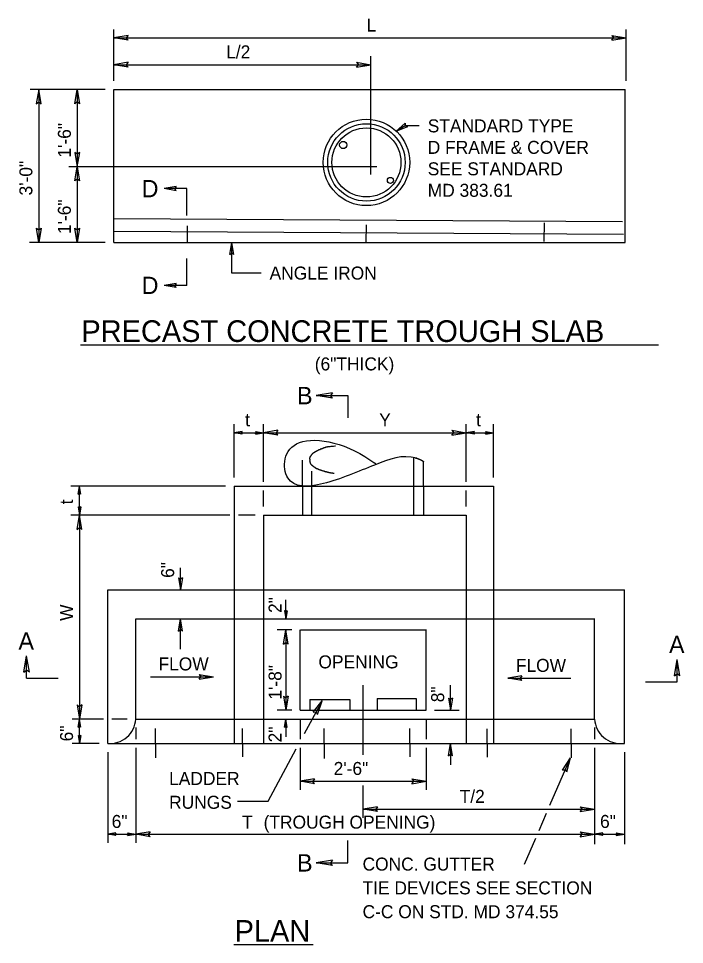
# Model space of a CAD drawing. Extents: x 5.8 to 18, y -5.2 to 5.4.
# Drawn here: x 5.94 to 9.015, y 0.977 to 5.255 of the extents above; entities that cross this region are included whole.
import ezdxf

# ---------------------------------------------------------------- set-up
doc = ezdxf.new("R2010")
doc.units = 0
for name, color, linetype in [('DETL-DIMS', 7, 'Continuous'), ('DETL-LINE', 7, 'Continuous'), ('DETL-NOTE', 7, 'Continuous'), ('DETL-TITL', 7, 'Continuous')]:
    doc.layers.add(name, color=color, linetype=linetype)

msp = doc.modelspace()

# ---------------------------------------------------------------- linework, layer by layer
at = {"layer": 'DETL-DIMS'}
for p, q in [((6.3798, 4.9667), (6.3798, 5.205)), ((6.4456, 5.1768), (6.3798, 5.1658)), ((6.4456, 5.1768), (6.4374, 5.1658)), ((8.6793, 5.1768), (8.7452, 5.1658)), ((8.6793, 5.1768), (8.6876, 5.1658)), ((8.7452, 4.9667), (8.7452, 5.205)), ((6.3798, 5.1658), (8.7452, 5.1658)), ((6.4456, 5.1548), (6.3798, 5.1658)), ((6.4456, 5.1548), (6.4374, 5.1658)), ((8.6793, 5.1548), (8.7452, 5.1658)), ((8.6793, 5.1548), (8.6876, 5.1658)), ((6.4456, 5.0529), (6.3798, 5.0419)), ((6.4456, 5.0529), (6.4374, 5.0419)), ((7.501, 5.0529), (7.5669, 5.0419)), ((7.501, 5.0529), (7.5092, 5.0419)), ((7.5669, 4.5349), (7.5669, 5.0811)), ((6.3798, 5.0419), (7.5669, 5.0419)), ((6.4456, 5.0309), (6.3798, 5.0419)), ((6.4456, 5.0309), (6.4374, 5.0419)), ((7.501, 5.0309), (7.5669, 5.0419)), ((7.501, 5.0309), (7.5092, 5.0419)), ((6.3405, 4.9274), (5.9938, 4.9274)), ((6.0331, 4.9274), (6.0217, 4.8616)), ((6.0331, 4.9274), (6.0329, 4.2209)), ((6.0436, 4.8615), (6.0331, 4.9274)), ((6.1995, 4.8616), (6.2108, 4.9274)), ((6.2108, 4.9274), (6.2107, 4.5707)), ((6.2108, 4.9274), (6.2214, 4.8615)), ((6.0217, 4.8616), (6.0327, 4.8698)), ((6.0327, 4.8698), (6.0436, 4.8615)), ((6.2105, 4.8698), (6.1995, 4.8616)), ((6.2214, 4.8615), (6.2105, 4.8698)), ((7.6825, 4.7332), (7.7256, 4.771)), ((7.7245, 4.7592), (7.6825, 4.7332)), ((7.7355, 4.755), (7.6825, 4.7332)), ((7.7256, 4.771), (7.7245, 4.7592)), ((7.7245, 4.7592), (7.7355, 4.755)), ((7.7903, 4.7592), (7.7245, 4.7592)), ((6.2111, 4.6283), (6.2002, 4.6367)), ((6.2002, 4.6367), (6.2107, 4.5707)), ((6.2107, 4.5707), (6.2221, 4.6365)), ((6.2221, 4.6365), (6.2111, 4.6283)), ((7.5947, 4.5707), (6.1715, 4.5707)), ((6.1994, 4.5049), (6.2107, 4.5707)), ((6.2107, 4.5707), (6.2213, 4.5047)), ((6.2107, 4.5707), (6.2107, 4.2209)), ((6.2104, 4.513), (6.1994, 4.5049)), ((6.2213, 4.5047), (6.2104, 4.513)), ((6.6684, 4.4787), (6.612, 4.4692)), ((6.7164, 4.4692), (6.612, 4.4692)), ((6.6684, 4.4598), (6.612, 4.4692)), ((6.6684, 4.4787), (6.6614, 4.4692)), ((6.6684, 4.4598), (6.6614, 4.4692)), ((6.7164, 4.3452), (6.7164, 4.4692)), ((6.0329, 4.2209), (6.0223, 4.2868)), ((6.0223, 4.2868), (6.0333, 4.2785)), ((6.0443, 4.2867), (6.0329, 4.2209)), ((6.0333, 4.2785), (6.0443, 4.2867)), ((6.2107, 4.2209), (6.2001, 4.2868)), ((6.2001, 4.2868), (6.211, 4.2785)), ((6.222, 4.2867), (6.2107, 4.2209)), ((6.211, 4.2785), (6.222, 4.2867)), ((6.3405, 4.2209), (5.9897, 4.2209)), ((6.9151, 4.1644), (6.9245, 4.2209)), ((6.9245, 4.0792), (6.9245, 4.2209)), ((6.9339, 4.1644), (6.9245, 4.2209)), ((6.9151, 4.1644), (6.9245, 4.1714)), ((6.9339, 4.1644), (6.9245, 4.1714)), ((6.7164, 4.0223), (6.7164, 4.1463)), ((7.0599, 4.0792), (6.9245, 4.0792)), ((6.6684, 4.0317), (6.612, 4.0223)), ((6.7164, 4.0223), (6.612, 4.0223)), ((6.6684, 4.0129), (6.612, 4.0223)), ((6.6684, 4.0317), (6.6614, 4.0223)), ((6.6684, 4.0129), (6.6614, 4.0223)), ((7.3896, 3.5257), (7.3144, 3.5131)), ((7.3144, 3.5131), (7.46, 3.5131)), ((7.3896, 3.5006), (7.3144, 3.5131)), ((7.3896, 3.5257), (7.3802, 3.5131)), ((7.3896, 3.5006), (7.3802, 3.5131)), ((7.46, 3.5131), (7.46, 3.4104)), ((6.9352, 3.1341), (6.9352, 3.381)), ((7.0717, 3.1145), (7.0717, 3.381)), ((8.007, 3.1145), (8.007, 3.381)), ((8.1335, 3.1341), (8.1335, 3.381)), ((6.9729, 3.348), (6.9352, 3.3418)), ((6.9352, 3.3418), (7.0717, 3.3418)), ((6.9729, 3.3355), (6.9352, 3.3418)), ((6.9729, 3.348), (6.9682, 3.3418)), ((6.9729, 3.3355), (6.9682, 3.3418)), ((7.034, 3.348), (7.0717, 3.3418)), ((7.034, 3.348), (7.0387, 3.3418)), ((7.034, 3.3355), (7.0717, 3.3418)), ((7.034, 3.3355), (7.0387, 3.3418)), ((7.1376, 3.3527), (7.0717, 3.3418)), ((7.0717, 3.3418), (8.007, 3.3418)), ((7.1376, 3.3308), (7.0717, 3.3418)), ((7.1376, 3.3527), (7.1293, 3.3418)), ((7.1376, 3.3308), (7.1293, 3.3418)), ((7.9411, 3.3527), (8.007, 3.3418)), ((7.9411, 3.3527), (7.9494, 3.3418)), ((7.9411, 3.3308), (8.007, 3.3418)), ((7.9411, 3.3308), (7.9494, 3.3418)), ((8.0447, 3.348), (8.007, 3.3418)), ((8.007, 3.3418), (8.1335, 3.3418)), ((8.0447, 3.3355), (8.007, 3.3418)), ((8.0447, 3.348), (8.04, 3.3418)), ((8.0447, 3.3355), (8.04, 3.3418)), ((8.0958, 3.348), (8.1335, 3.3418)), ((8.0958, 3.348), (8.1005, 3.3418)), ((8.0958, 3.3355), (8.1335, 3.3418)), ((8.0958, 3.3355), (8.1005, 3.3418)), ((6.896, 3.0949), (6.1815, 3.0949)), ((6.2145, 3.0573), (6.2207, 3.0949)), ((6.2207, 2.961), (6.2207, 3.0949)), ((6.227, 3.0573), (6.2207, 3.0949)), ((6.2145, 3.0573), (6.2207, 3.062)), ((6.227, 3.0573), (6.2207, 3.062)), ((7.0717, 3.0002), (7.0717, 3.0753)), ((8.007, 3.0002), (8.007, 3.0753)), ((6.2145, 2.9987), (6.2207, 2.961)), ((6.2145, 2.9987), (6.2207, 2.994)), ((6.227, 2.9987), (6.2207, 2.961)), ((6.227, 2.9987), (6.2207, 2.994)), ((6.9156, 2.961), (6.1815, 2.961)), ((6.2098, 2.8951), (6.2207, 2.961)), ((6.2317, 2.8951), (6.2207, 2.961)), ((6.2207, 2.961), (6.2207, 2.0182)), ((7.0325, 2.961), (6.9548, 2.961)), ((6.2098, 2.8951), (6.2207, 2.9034)), ((6.2317, 2.8951), (6.2207, 2.9034)), ((6.6876, 2.6154), (6.6876, 2.7173)), ((6.6782, 2.6718), (6.6876, 2.6154)), ((6.6782, 2.6718), (6.6876, 2.6648)), ((6.697, 2.6718), (6.6876, 2.6154)), ((6.697, 2.6718), (6.6876, 2.6648)), ((7.1741, 2.4819), (7.1741, 2.5697)), ((6.6782, 2.4254), (6.6876, 2.4819)), ((6.6876, 2.3418), (6.6876, 2.4819)), ((6.697, 2.4254), (6.6876, 2.4819)), ((7.168, 2.5196), (7.1741, 2.4819)), ((7.168, 2.5196), (7.1743, 2.5149)), ((7.1806, 2.5195), (7.1741, 2.4819)), ((7.1806, 2.5195), (7.1743, 2.5149)), ((6.6782, 2.4254), (6.6876, 2.4325)), ((6.697, 2.4254), (6.6876, 2.4325)), ((7.2013, 2.4306), (7.1349, 2.4306)), ((7.1627, 2.3648), (7.1741, 2.4306)), ((7.1846, 2.3646), (7.1741, 2.4306)), ((7.1741, 2.4306), (7.1741, 2.0592)), ((7.1627, 2.3648), (7.1737, 2.3729)), ((7.1846, 2.3646), (7.1737, 2.3729)), ((5.9645, 2.2351), (5.977, 2.3104)), ((5.977, 2.2074), (5.977, 2.3104)), ((5.9896, 2.2351), (5.977, 2.3104)), ((8.9691, 2.2186), (8.9816, 2.2939)), ((8.9816, 2.1909), (8.9816, 2.2939)), ((8.9942, 2.2186), (8.9816, 2.2939)), ((5.9645, 2.2351), (5.977, 2.2445)), ((5.9896, 2.2351), (5.977, 2.2445)), ((6.7736, 2.225), (6.8395, 2.214)), ((6.7736, 2.225), (6.7819, 2.214)), ((8.9691, 2.2186), (8.9816, 2.228)), ((8.9942, 2.2186), (8.9816, 2.228)), ((5.977, 2.2074), (6.1227, 2.2074)), ((6.5485, 2.214), (6.8395, 2.214)), ((6.7736, 2.203), (6.8395, 2.214)), ((6.7736, 2.203), (6.7819, 2.214)), ((8.2646, 2.2184), (8.1987, 2.2074)), ((8.1987, 2.2074), (8.4899, 2.2074)), ((8.2646, 2.1964), (8.1987, 2.2074)), ((8.2646, 2.2184), (8.2564, 2.2074)), ((8.2646, 2.1964), (8.2564, 2.2074)), ((8.8359, 2.1909), (8.9816, 2.1909)), ((7.5314, 1.8537), (7.5314, 2.1756)), ((7.9347, 2.0592), (7.9347, 2.1754)), ((7.1635, 2.1252), (7.1741, 2.0592)), ((7.1635, 2.1252), (7.1745, 2.1169)), ((7.1855, 2.125), (7.1741, 2.0592)), ((7.1855, 2.125), (7.1745, 2.1169)), ((7.3413, 2.1029), (7.2591, 1.9502)), ((7.3004, 2.0501), (7.3413, 2.1029)), ((7.3197, 2.0397), (7.3413, 2.1029)), ((7.9253, 2.1157), (7.9347, 2.0592)), ((7.9253, 2.1157), (7.9347, 2.1086)), ((7.9442, 2.1157), (7.9347, 2.0592)), ((7.9442, 2.1157), (7.9347, 2.1086)), ((6.2098, 2.0841), (6.2207, 2.0182)), ((6.2098, 2.0841), (6.2207, 2.0759)), ((6.2317, 2.0841), (6.2207, 2.0182)), ((6.2317, 2.0841), (6.2207, 2.0759)), ((7.2013, 2.0592), (7.1349, 2.0592)), ((7.8615, 2.0592), (7.974, 2.0592)), ((6.3318, 2.0182), (6.1881, 2.0182)), ((6.2145, 1.9806), (6.2207, 2.0182)), ((6.2207, 1.9057), (6.2207, 2.0182)), ((6.227, 1.9806), (6.2207, 2.0182)), ((6.4418, 2.0182), (6.371, 2.0182)), ((7.1676, 1.9806), (7.1741, 2.0182)), ((7.1801, 1.9805), (7.1741, 2.0182)), ((7.1741, 2.0182), (7.1741, 1.9372)), ((7.2405, 2.02), (7.2405, 1.9253)), ((7.3004, 2.0501), (7.314, 2.0521)), ((7.3197, 2.0397), (7.314, 2.0521)), ((7.8223, 2.02), (7.8223, 1.9253)), ((6.2145, 1.9806), (6.2207, 1.9853)), ((6.227, 1.9806), (6.2207, 1.9853)), ((6.481, 1.979), (6.481, 1.9253)), ((7.1676, 1.9806), (7.1738, 1.9853)), ((7.1801, 1.9805), (7.1738, 1.9853)), ((8.5999, 1.979), (8.5999, 1.9253)), ((6.2145, 1.9433), (6.2207, 1.9057)), ((6.2145, 1.9433), (6.2207, 1.9386)), ((6.227, 1.9433), (6.2207, 1.9057)), ((6.227, 1.9433), (6.2207, 1.9386)), ((6.3122, 1.9057), (6.1881, 1.9057)), ((6.481, 1.8861), (6.481, 1.4472)), ((7.2405, 1.8861), (7.2405, 1.692)), ((7.8223, 1.8861), (7.8223, 1.692)), ((7.9253, 1.8492), (7.9347, 1.9057)), ((7.9442, 1.8492), (7.9347, 1.9057)), ((7.9347, 1.9057), (7.9347, 1.8076)), ((8.5999, 1.8861), (8.5999, 1.4406)), ((6.3514, 1.8665), (6.3514, 1.4472)), ((7.0921, 1.6396), (7.222, 1.8811)), ((7.9253, 1.8492), (7.9347, 1.8563)), ((7.9442, 1.8492), (7.9347, 1.8563)), ((8.7379, 1.8665), (8.7379, 1.4406)), ((8.3938, 1.6202), (8.4883, 1.8391)), ((8.4521, 1.7829), (8.4883, 1.8391)), ((8.4723, 1.7742), (8.4883, 1.8391)), ((8.4521, 1.7829), (8.4655, 1.7861)), ((8.4723, 1.7742), (8.4655, 1.7861)), ((7.3064, 1.7421), (7.2405, 1.7312)), ((7.2405, 1.7312), (7.8223, 1.7312)), ((7.3064, 1.7202), (7.2405, 1.7312)), ((7.3064, 1.7421), (7.2982, 1.7312)), ((7.3064, 1.7202), (7.2982, 1.7312)), ((7.5314, 1.563), (7.5314, 1.7122)), ((7.7564, 1.7421), (7.8223, 1.7312)), ((7.7564, 1.7421), (7.7646, 1.7312)), ((7.7564, 1.7202), (7.8223, 1.7312)), ((7.7564, 1.7202), (7.7646, 1.7312)), ((6.9504, 1.6396), (7.0921, 1.6396)), ((7.5973, 1.6132), (7.5314, 1.6022)), ((7.5314, 1.6022), (8.5999, 1.6022)), ((7.5973, 1.5912), (7.5314, 1.6022)), ((7.5973, 1.6132), (7.5891, 1.6022)), ((7.5973, 1.5912), (7.5891, 1.6022)), ((8.3438, 1.5044), (8.3783, 1.5842)), ((8.534, 1.6132), (8.5999, 1.6022)), ((8.534, 1.6132), (8.5423, 1.6022)), ((8.534, 1.5912), (8.5999, 1.6022)), ((8.534, 1.5912), (8.5423, 1.6022)), ((6.5469, 1.4974), (6.481, 1.4864)), ((6.5469, 1.4974), (6.5386, 1.4864)), ((8.534, 1.4974), (8.5999, 1.4864)), ((8.534, 1.4974), (8.5423, 1.4864)), ((6.389, 1.4927), (6.3514, 1.4864)), ((6.3514, 1.4864), (6.481, 1.4864)), ((6.389, 1.4801), (6.3514, 1.4864)), ((6.389, 1.4927), (6.3843, 1.4864)), ((6.389, 1.4801), (6.3843, 1.4864)), ((6.4433, 1.4927), (6.481, 1.4864)), ((6.4433, 1.4927), (6.448, 1.4864)), ((6.4433, 1.4801), (6.481, 1.4864)), ((6.4433, 1.4801), (6.448, 1.4864)), ((6.481, 1.4864), (8.5999, 1.4864)), ((6.5469, 1.4754), (6.481, 1.4864)), ((6.5469, 1.4754), (6.5386, 1.4864)), ((7.46, 1.3543), (7.46, 1.4573)), ((8.2766, 1.3488), (8.3283, 1.4684)), ((8.534, 1.4754), (8.5999, 1.4864)), ((8.534, 1.4754), (8.5423, 1.4864)), ((8.6376, 1.4927), (8.5999, 1.4864)), ((8.5999, 1.4864), (8.7379, 1.4864)), ((8.6376, 1.4801), (8.5999, 1.4864)), ((8.6376, 1.4927), (8.6329, 1.4864)), ((8.6376, 1.4801), (8.6329, 1.4864)), ((8.7002, 1.4927), (8.7379, 1.4864)), ((8.7002, 1.4927), (8.7049, 1.4864)), ((8.7002, 1.4801), (8.7379, 1.4864)), ((8.7002, 1.4801), (8.7049, 1.4864)), ((7.3896, 1.3668), (7.3144, 1.3543)), ((7.3144, 1.3543), (7.46, 1.3543)), ((7.3896, 1.3417), (7.3144, 1.3543)), ((7.3896, 1.3668), (7.3802, 1.3543)), ((7.3896, 1.3417), (7.3802, 1.3543))]:
    msp.add_line(p, q, dxfattribs=at)
at = {"layer": 'DETL-LINE'}
for p, q in [((6.3798, 4.9274), (8.7409, 4.9274)), ((6.3798, 4.2209), (6.3798, 4.9274)), ((8.7409, 4.2209), (8.7409, 4.9274)), ((6.3796, 4.3316), (8.7284, 4.3174)), ((6.7199, 4.2221), (6.7204, 4.2971)), ((7.5458, 4.219), (7.5463, 4.3024)), ((8.3675, 4.2249), (8.368, 4.3117)), ((6.3815, 4.2732), (8.7333, 4.259)), ((6.3798, 4.2209), (8.7409, 4.2209)), ((7.2505, 3.0949), (7.2505, 3.2145)), ((7.766, 2.961), (7.766, 3.2272)), ((7.8101, 3.0949), (7.8101, 3.2089)), ((7.2944, 2.961), (7.2944, 3.1635)), ((6.9352, 3.0949), (8.1335, 3.0949)), ((6.9352, 3.0949), (6.9352, 2.6154)), ((7.2505, 3.0949), (7.2505, 2.961)), ((7.8101, 3.0949), (7.8101, 2.961)), ((8.1335, 3.0949), (8.1335, 2.6154)), ((7.0717, 2.961), (8.007, 2.961)), ((7.0717, 2.961), (7.0717, 1.9057)), ((8.007, 2.961), (8.007, 1.9057)), ((6.3514, 1.9057), (6.3514, 2.6154)), ((6.3514, 2.6154), (8.7379, 2.6154)), ((6.9352, 2.6154), (6.9352, 1.9057)), ((8.1335, 2.6154), (8.1335, 1.9057)), ((8.7379, 1.9057), (8.7379, 2.6154)), ((6.481, 2.4819), (8.6019, 2.4819)), ((6.481, 2.0182), (6.481, 2.4819)), ((8.5999, 2.0182), (8.5999, 2.4819)), ((7.2405, 2.0592), (7.2405, 2.4306)), ((7.2422, 2.4306), (7.8239, 2.4306)), ((7.8223, 2.0592), (7.8223, 2.4306)), ((7.285, 2.1095), (7.4703, 2.1095)), ((7.285, 2.1095), (7.285, 2.0592)), ((7.4703, 2.1095), (7.4703, 2.0592)), ((7.5954, 2.1142), (7.7755, 2.1142)), ((7.5954, 2.1142), (7.5954, 2.0592)), ((7.7755, 2.1142), (7.7755, 2.0592)), ((7.2405, 2.0592), (7.8223, 2.0592)), ((6.481, 2.0182), (8.5999, 2.0182)), ((6.5728, 1.9057), (6.5728, 1.9751)), ((6.9747, 1.9057), (6.9747, 1.9751)), ((7.3511, 1.9057), (7.3511, 1.9751)), ((7.7466, 1.9057), (7.7466, 1.9755)), ((8.1044, 1.9057), (8.1044, 1.973)), ((8.4925, 1.9057), (8.4925, 1.973)), ((6.3514, 1.9057), (8.7379, 1.9057)), ((6.5728, 1.9057), (6.5728, 1.8392)), ((6.9747, 1.9057), (6.9747, 1.844)), ((7.3511, 1.9057), (7.3511, 1.8372)), ((7.7466, 1.9057), (7.7466, 1.8445)), ((8.1044, 1.9057), (8.1044, 1.842)), ((8.4925, 1.9057), (8.4925, 1.8403))]:
    msp.add_line(p, q, dxfattribs=at)
for centre, radius in [((7.5463, 4.5904), 0.1998), ((7.5463, 4.5904), 0.1789), ((7.5463, 4.5904), 0.1595), ((7.4393, 4.6709), 0.0168), ((7.6572, 4.507), 0.0141)]:
    msp.add_circle(centre, radius, dxfattribs=at)
for centre, radius, start, end in [((7.5718, 3.1822), 0.0228, 39.7234, 53.0048), ((6.3609, 2.0256), 0.1203, 265.4444, 356.4964), ((8.72, 2.0256), 0.1203, 183.5036, 274.5556)]:
    msp.add_arc(centre, radius, start, end, dxfattribs=at)
msp.add_open_spline([(7.7789, 3.2245), (7.7091, 3.2416), (7.601, 3.2011), (7.3347, 3.0883), (7.151, 3.0873), (7.1645, 3.3583), (7.4666, 3.2927), (7.5855, 3.2003)], degree=3, dxfattribs=at)
for points in [[(7.4041, 3.2789), (7.4002, 3.2789), (7.3878, 3.2776), (7.3766, 3.277), (7.3694, 3.2763), (7.3675, 3.2763), (7.3668, 3.2756), (7.3635, 3.275), (7.3622, 3.275), (7.3609, 3.2743), (7.3596, 3.2743), (7.3589, 3.2737), (7.3583, 3.2737), (7.357, 3.2731), (7.3563, 3.2731), (7.3544, 3.2724), (7.3531, 3.2717), (7.3524, 3.2717), (7.3498, 3.2711), (7.3491, 3.2704), (7.3478, 3.2704), (7.3465, 3.2698), (7.3458, 3.2691), (7.3445, 3.2691), (7.3419, 3.2678), (7.34, 3.2671), (7.3393, 3.2665), (7.3367, 3.2658), (7.336, 3.2658), (7.3341, 3.2652), (7.3327, 3.2645), (7.3321, 3.2639), (7.3288, 3.2625), (7.3282, 3.2619), (7.3269, 3.2619), (7.3256, 3.2612), (7.3249, 3.2606), (7.3242, 3.2606), (7.3203, 3.2586), (7.3196, 3.258), (7.319, 3.258), (7.3177, 3.2573), (7.317, 3.2567), (7.3157, 3.256), (7.3138, 3.2547), (7.3125, 3.2547), (7.3111, 3.2534), (7.3105, 3.2534), (7.3098, 3.2527), (7.3085, 3.2521), (7.3079, 3.2514), (7.3065, 3.2514), (7.3046, 3.2494), (7.3026, 3.2481), (7.302, 3.2475), (7.3007, 3.2469), (7.3, 3.2469), (7.298, 3.2449), (7.2967, 3.2442), (7.2961, 3.2436), (7.2948, 3.2416), (7.2941, 3.2409), (7.2928, 3.2403), (7.2922, 3.2396), (7.2922, 3.239), (7.2909, 3.2377), (7.2909, 3.237), (7.2889, 3.2351), (7.2876, 3.2324), (7.2876, 3.2318), (7.2863, 3.2311), (7.2856, 3.2298), (7.2856, 3.2292), (7.2849, 3.2285), (7.2849, 3.2272), (7.2843, 3.2259), (7.2836, 3.2239), (7.2836, 3.2226), (7.2843, 3.2134), (7.2843, 3.2102), (7.2849, 3.2095), (7.2849, 3.2076), (7.2856, 3.2069), (7.2856, 3.2062), (7.2856, 3.2049), (7.2856, 3.2043), (7.2863, 3.203), (7.2869, 3.2023), (7.2869, 3.2003), (7.2876, 3.1997), (7.2876, 3.1991), (7.2882, 3.1984), (7.2889, 3.1971), (7.2915, 3.1945), (7.2922, 3.1931), (7.2928, 3.1925), (7.2935, 3.1925)], [(7.7715, 3.2252), (7.7728, 3.2252), (7.7741, 3.2246), (7.776, 3.2246), (7.776, 3.2239), (7.778, 3.2239), (7.778, 3.2233), (7.7793, 3.2233), (7.7806, 3.2226), (7.782, 3.2226), (7.7826, 3.222), (7.7845, 3.222), (7.7852, 3.2213), (7.7865, 3.2213), (7.7872, 3.2207), (7.7878, 3.2207), (7.7885, 3.22), (7.7905, 3.22), (7.7911, 3.2193), (7.7918, 3.2193), (7.7924, 3.2187), (7.7931, 3.2187), (7.7944, 3.218), (7.7951, 3.218), (7.7951, 3.2174), (7.7964, 3.2174), (7.7964, 3.2167), (7.7976, 3.2167), (7.7983, 3.2161), (7.799, 3.2161), (7.8003, 3.2147), (7.8009, 3.2147), (7.8009, 3.2141), (7.8016, 3.2141), (7.8022, 3.2141), (7.8022, 3.2134), (7.8036, 3.2134), (7.8036, 3.2128), (7.8042, 3.2128), (7.8042, 3.2121), (7.8055, 3.2121), (7.8055, 3.2115), (7.8062, 3.2115), (7.8075, 3.2102), (7.8082, 3.2102), (7.8088, 3.2102), (7.8088, 3.2095), (7.8095, 3.2095), (7.8101, 3.2089)], [(7.2935, 3.1925), (7.2954, 3.1905), (7.2961, 3.1905), (7.2987, 3.1879), (7.3, 3.1872), (7.3013, 3.186), (7.3026, 3.1853), (7.3033, 3.1846), (7.304, 3.1846), (7.3053, 3.1833), (7.3059, 3.1833), (7.3065, 3.1827), (7.3079, 3.182), (7.3085, 3.1814), (7.3098, 3.1807), (7.3098, 3.18), (7.3105, 3.18), (7.3111, 3.1794), (7.3125, 3.1787), (7.3138, 3.1774), (7.3157, 3.1768), (7.317, 3.1761), (7.3177, 3.1761), (7.3203, 3.1748), (7.3216, 3.1741), (7.3223, 3.1741), (7.3236, 3.1735), (7.3242, 3.1729), (7.3249, 3.1729), (7.3262, 3.1722), (7.3282, 3.1722), (7.3282, 3.1715), (7.3288, 3.1715), (7.3301, 3.1709), (7.3315, 3.1709), (7.3321, 3.1702), (7.3327, 3.1702), (7.3341, 3.1696), (7.3354, 3.1696), (7.3367, 3.1689), (7.338, 3.1689), (7.3386, 3.1683), (7.3393, 3.1683), (7.3406, 3.1676), (7.3419, 3.1676), (7.3426, 3.167), (7.3439, 3.1663), (7.3458, 3.1663), (7.3465, 3.1656), (7.3472, 3.1656), (7.3478, 3.165), (7.3498, 3.165), (7.3511, 3.1643), (7.3517, 3.1643), (7.3524, 3.1637), (7.3537, 3.1637), (7.3544, 3.163), (7.3557, 3.163), (7.3557, 3.1624), (7.3583, 3.1617), (7.3609, 3.1617), (7.3616, 3.1611), (7.3622, 3.1611), (7.3635, 3.1611), (7.3642, 3.1604), (7.3655, 3.1604), (7.3662, 3.1598), (7.3675, 3.1598), (7.3688, 3.1591), (7.3714, 3.1591), (7.372, 3.1584), (7.3733, 3.1584), (7.374, 3.1584), (7.3753, 3.1578), (7.3766, 3.1578), (7.3786, 3.1571), (7.3799, 3.1571), (7.3825, 3.1565), (7.3858, 3.1565), (7.3864, 3.1558), (7.3884, 3.1558), (7.3904, 3.1558), (7.3917, 3.1552), (7.3969, 3.1552)]]:
    msp.add_spline(points, degree=3, dxfattribs=at)
at = {"layer": 'DETL-TITL'}
for p, q in [((6.2253, 3.7483), (8.8955, 3.7483)), ((6.9342, 0.9773), (7.3005, 0.9773))]:
    msp.add_line(p, q, dxfattribs=at)

# ---------------------------------------------------------------- texts
at = {"layer": 'DETL-NOTE'}
for s, p in [('L', (7.5478, 5.1952)), ('L/2', (6.8986, 5.0713)), ('STANDARD TYPE', (7.8295, 4.7292)), ('D FRAME & COVER', (7.8295, 4.63)), ('SEE STANDARD', (7.8295, 4.5308)), ('MD 383.61', (7.8295, 4.4316)), ('ANGLE IRON', (7.0991, 4.0492)), ('(6"THICK)', (7.3078, 3.6295)), ('t', (6.9862, 3.3712)), ('Y', (7.6053, 3.3712)), ('t', (8.053, 3.3712)), ('OPENING', (7.3247, 2.2529)), ('FLOW', (6.5861, 2.2434)), ('FLOW', (8.2364, 2.2368)), ('2\'-6"', (7.3951, 1.7606)), ('LADDER', (6.6351, 1.7142)), ('T/2', (7.977, 1.6316)), ('RUNGS', (6.6351, 1.6042)), ('6"', (6.3698, 1.5158)), ('T', (6.9721, 1.5125)), ('(TROUGH OPENING)', (7.0715, 1.5125)), ('6"', (8.6253, 1.5158)), ('CONC. GUTTER', (7.5285, 1.3188)), ('TIE DEVICES SEE SECTION', (7.5285, 1.2088)), ('C-C ON STD. MD 374.55', (7.5285, 1.0988))]:
    msp.add_text(s, height=0.06, dxfattribs=at).set_placement(p)
for s, p in [('1\'-6"', (6.1814, 4.6128)), ('3\'-0"', (6.0036, 4.4378)), ('1\'-6"', (6.1813, 4.2594)), ('t', (6.1913, 3.0107)), ('6"', (6.6582, 2.6709)), ('2"', (7.1545, 2.5089)), ('W', (6.1913, 2.4723)), ('1\'-8"', (7.1545, 2.1086)), ('8"', (7.9053, 2.0963)), ('6"', (6.1913, 1.9156)), ('2"', (7.1545, 1.9109))]:
    msp.add_text(s, height=0.06, rotation=90, dxfattribs=at).set_placement(p)
at = {"layer": 'DETL-TITL'}
for s, height, p in [('D', 0.08, (6.5087, 4.4292)), ('D', 0.08, (6.5087, 3.9823)), ('PRECAST CONCRETE TROUGH SLAB', 0.1, (6.2301, 3.761)), ('B', 0.08, (7.2262, 3.4731)), ('A', 0.08, (5.9395, 2.3398)), ('A', 0.08, (8.944, 2.3233)), ('B', 0.08, (7.2262, 1.3143)), ('PLAN', 0.1, (6.9376, 0.99))]:
    msp.add_text(s, height=height, dxfattribs=at).set_placement(p)

doc.saveas('drawing.dxf')
